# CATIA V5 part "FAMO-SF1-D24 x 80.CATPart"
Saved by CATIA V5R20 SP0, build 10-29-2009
Part number: FAMO-SF1-D24 x 80
Definition: NONE
Nomenclature: FAMO-SF1-D24 x 80
Source: Unknown
Description: FAMO-SF1-D24 x 80
Bounding box of the stored display mesh (mm): x -48 to 32, y -22 to 22, z -22 to 22
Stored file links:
  C:\Users\Utente\Desktop\IO LAVORO\3D X SITO CF\X SITO\FAMO\FAMO-SF1-D24 x 80.CATPart
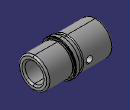
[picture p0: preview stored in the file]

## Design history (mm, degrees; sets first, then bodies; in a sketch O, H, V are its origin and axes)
Body1 "FAMO-SF1-D24 x 80" (main body)
  Solid1: solid without history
